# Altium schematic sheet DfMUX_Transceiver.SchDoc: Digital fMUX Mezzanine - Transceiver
size 246 x 182 mm; Engineer: M.Dobbs, McGill U.; Revision: 4
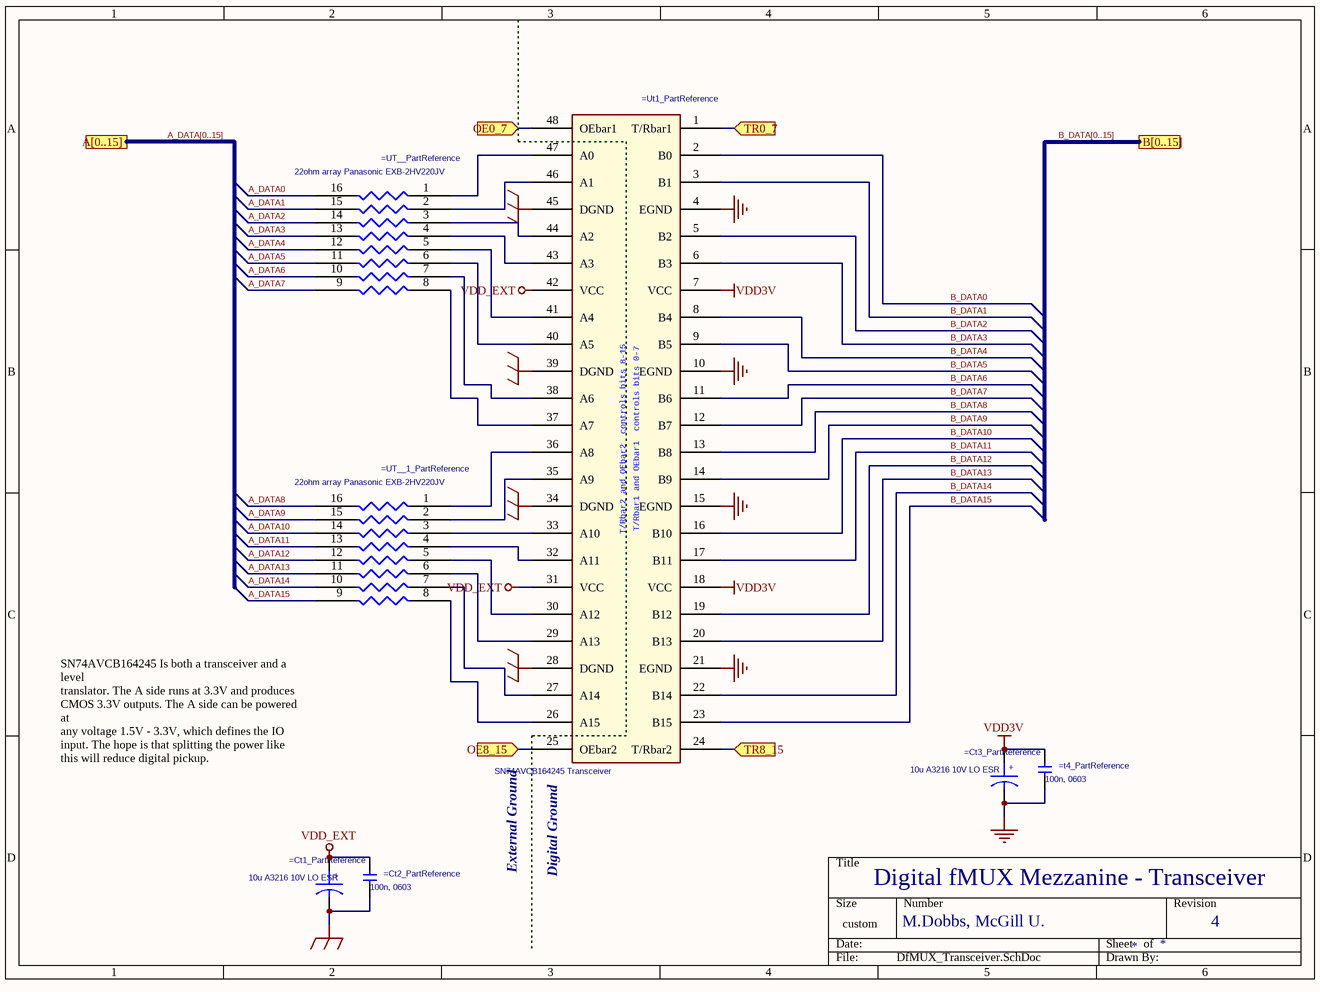
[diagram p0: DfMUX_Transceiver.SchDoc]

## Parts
=Ct1_PartReference  10u A3216 10V LO ESR  [TANTA]
=Ct2_PartReference  100n, 0603  [CK05]
=Ct3_PartReference  10u A3216 10V LO ESR  [TANTA]
=t4_PartReference  100n, 0603  [CK05]
=Ut1_PartReference  SN74AVCB164245 Transceiver  [TSSOP48]
=UT__1_PartReference  22ohm array Panasonic EXB-2HV220JV  [RN8.150X63]
=UT__PartReference  22ohm array Panasonic EXB-2HV220JV  [RN8.150X63]

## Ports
A[0..15], B[0..15], OE0_7, OE8_15, TR0_7, TR8_15

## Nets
GND_DIG: =Ct3_PartReference.2 =t4_PartReference.1 =Ut1_PartReference.4(EGND) =Ut1_PartReference.10(EGND) =Ut1_PartReference.15(EGND) =Ut1_PartReference.21(EGND)
GND_EARTH: =Ct1_PartReference.2 =Ct2_PartReference.1 =Ut1_PartReference.28(DGND) =Ut1_PartReference.34(DGND) =Ut1_PartReference.39(DGND) =Ut1_PartReference.45(DGND)
VDD3V: =Ct3_PartReference.1 =t4_PartReference.2 =Ut1_PartReference.7(VCC) =Ut1_PartReference.18(VCC)
VDD_EXT: =Ct1_PartReference.1 =Ct2_PartReference.2 =Ut1_PartReference.31(VCC) =Ut1_PartReference.42(VCC)
A_DATA0: =UT__PartReference.16(R1)
A_DATA1: =UT__PartReference.15(R2)
A_DATA2: =UT__PartReference.14(R3)
A_DATA3: =UT__PartReference.13(R4)
A_DATA4: =UT__PartReference.12(R5)
A_DATA5: =UT__PartReference.11(R6)
A_DATA6: =UT__PartReference.10(R7)
A_DATA7: =UT__PartReference.9(R8)
A_DATA8: =UT__1_PartReference.16(R1)
A_DATA9: =UT__1_PartReference.15(R2)
A_DATA10: =UT__1_PartReference.14(R3)
A_DATA11: =UT__1_PartReference.13(R4)
A_DATA12: =UT__1_PartReference.12(R5)
A_DATA13: =UT__1_PartReference.11(R6)
A_DATA14: =UT__1_PartReference.10(R7)
A_DATA15: =UT__1_PartReference.9(R8)
B_DATA0: =Ut1_PartReference.2(B0)
B_DATA1: =Ut1_PartReference.3(B1)
B_DATA2: =Ut1_PartReference.5(B2)
B_DATA3: =Ut1_PartReference.6(B3)
B_DATA4: =Ut1_PartReference.8(B4)
B_DATA5: =Ut1_PartReference.9(B5)
B_DATA6: =Ut1_PartReference.11(B6)
B_DATA7: =Ut1_PartReference.12(B7)
B_DATA8: =Ut1_PartReference.13(B8)
B_DATA9: =Ut1_PartReference.14(B9)
B_DATA10: =Ut1_PartReference.16(B10)
B_DATA11: =Ut1_PartReference.17(B11)
B_DATA12: =Ut1_PartReference.19(B12)
B_DATA13: =Ut1_PartReference.20(B13)
B_DATA14: =Ut1_PartReference.22(B14)
B_DATA15: =Ut1_PartReference.23(B15)
OE0_7: =Ut1_PartReference.48(OEbar1) ; port OE0_7
OE8_15: =Ut1_PartReference.25(OEbar2) ; port OE8_15
TR0_7: =Ut1_PartReference.1(T/Rbar1) ; port TR0_7
TR8_15: =Ut1_PartReference.24(T/Rbar2) ; port TR8_15
Net=Ut1_PartReference_26: =Ut1_PartReference.26(A15) =UT__1_PartReference.8(R8)
Net=Ut1_PartReference_27: =Ut1_PartReference.27(A14) =UT__1_PartReference.7(R7)
Net=Ut1_PartReference_29: =Ut1_PartReference.29(A13) =UT__1_PartReference.6(R6)
Net=Ut1_PartReference_30: =Ut1_PartReference.30(A12) =UT__1_PartReference.5(R5)
Net=Ut1_PartReference_32: =Ut1_PartReference.32(A11) =UT__1_PartReference.4(R4)
Net=Ut1_PartReference_33: =Ut1_PartReference.33(A10) =UT__1_PartReference.3(R3)
Net=Ut1_PartReference_35: =Ut1_PartReference.35(A9) =UT__1_PartReference.2(R2)
Net=Ut1_PartReference_36: =Ut1_PartReference.36(A8) =UT__1_PartReference.1(R1)
Net=Ut1_PartReference_37: =Ut1_PartReference.37(A7) =UT__PartReference.8(R8)
Net=Ut1_PartReference_38: =Ut1_PartReference.38(A6) =UT__PartReference.7(R7)
Net=Ut1_PartReference_40: =Ut1_PartReference.40(A5) =UT__PartReference.6(R6)
Net=Ut1_PartReference_41: =Ut1_PartReference.41(A4) =UT__PartReference.5(R5)
Net=Ut1_PartReference_43: =Ut1_PartReference.43(A3) =UT__PartReference.4(R4)
Net=Ut1_PartReference_44: =Ut1_PartReference.44(A2) =UT__PartReference.3(R3)
Net=Ut1_PartReference_46: =Ut1_PartReference.46(A1) =UT__PartReference.2(R2)
Net=Ut1_PartReference_47: =Ut1_PartReference.47(A0) =UT__PartReference.1(R1)

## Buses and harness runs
bus A_DATA[0..15] = port A[0..15]
bus B_DATA[0..15] = port B[0..15]

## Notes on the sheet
- SN74AVCB164245 Is both a transceiver and a level
  translator. The A side runs at 3.3V and produces
  CMOS 3.3V outputs. The A side can be powered at
  any voltage 1.5V - 3.3V, which defines the IO
  input. The hope is that splitting the power like
  this will reduce digital pickup.
- (near =Ut1_PartReference) External Ground
- (near =Ut1_PartReference) Digital Ground

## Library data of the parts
=Ct1_PartReference =Ct3_PartReference = CAPACITOR POL: COMPFIXED: NO; COMPGROUP: 0; COMPHEIGHT: 0.000; COMPROT: 270; COMPSIDE: TOP
=Ct2_PartReference = C: PSpiceTemplate: C^@REFDES %1 %2 ?TOLERANCE|C^@REFDES| @VALUE ?IC/IC=@IC/ ?TOLERANCE|\n.model C^@REFDES CAP C=1 DEV=@TOLERANCE%|; COMPFIXED: NO; COMPGROUP: 0; COMPHEIGHT: 0.000; COMPSIDE: TOP
=t4_PartReference = C: PSpiceTemplate: C^@REFDES %1 %2 ?TOLERANCE|C^@REFDES| @VALUE ?IC/IC=@IC/ ?TOLERANCE|\n.model C^@REFDES CAP C=1 DEV=@TOLERANCE%|; COMPFIXED: NO; COMPGROUP: 0; COMPHEIGHT: 0.000; COMPROT: 90; COMPSIDE: TOP
=Ut1_PartReference = 74LVT16245 Transceiver_0: COMPFIXED: NO; COMPGROUP: 0; COMPHEIGHT: 0.000; COMPROT: 90; COMPSIDE: BOT; FPLIST: TSSOP48_.4MMPITCH,TSSOP48_.4MMPITCH_NARROW
=UT__1_PartReference =UT__PartReference = R-PACK: COMPFIXED: NO; COMPGROUP: 0; COMPHEIGHT: 0.000; COMPROT: 90; COMPSIDE: BOT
